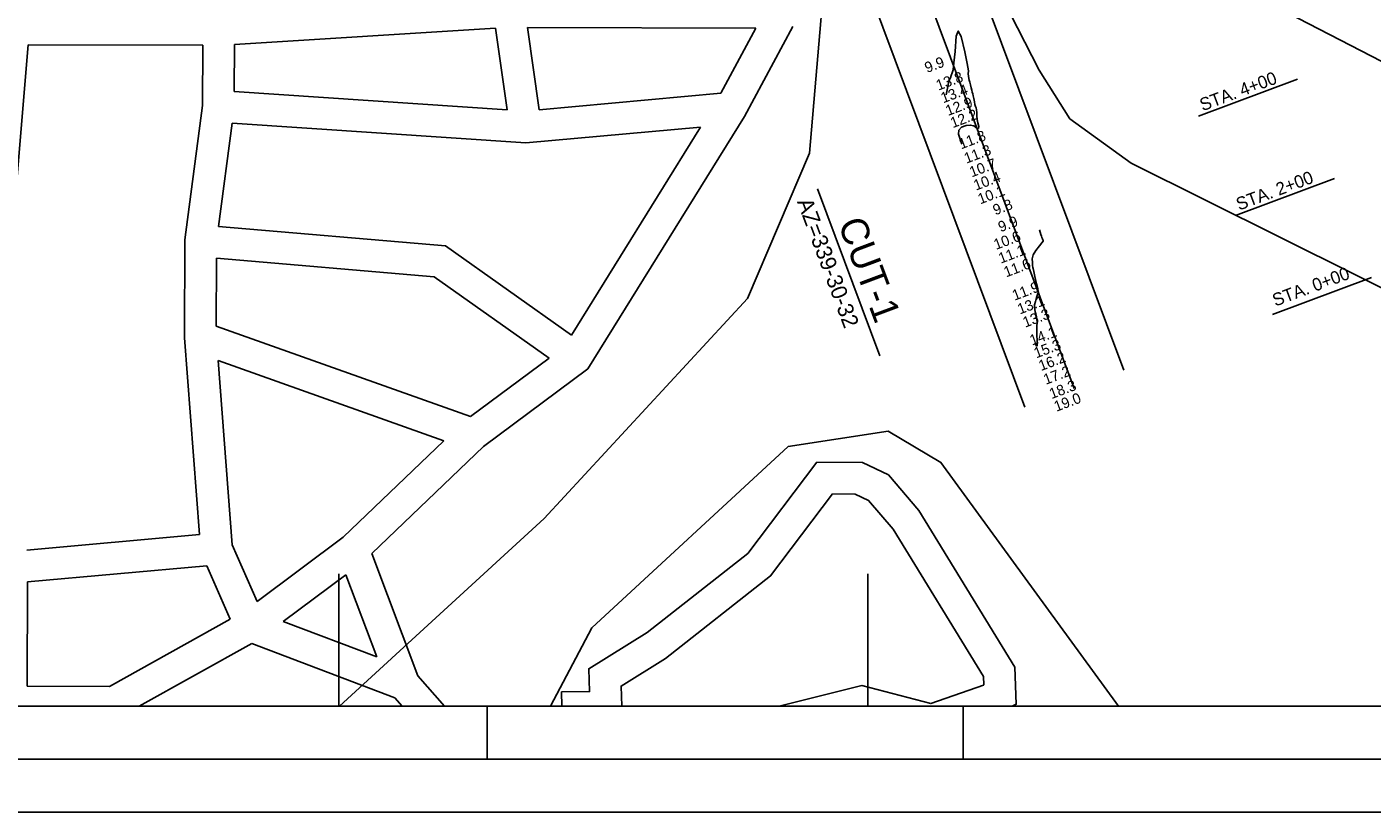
# Model space of a CAD drawing. Extents: x 503330 to 511530, y 1310349 to 1316149.
# Drawn here: x 506410 to 508954, y 1310349 to 1311832 of the extents above; entities that cross this region are included whole.
import ezdxf

# ---------------------------------------------------------------- set-up
doc = ezdxf.new("R2010")
doc.units = 0
for name, color, linetype in [('G-ANNO-TTLB', 7, 'Continuous'), ('Level 1', 7, 'Continuous'), ('Level 2', 7, 'Continuous'), ('Level 32', 7, 'Continuous'), ('Level 49', 7, 'Continuous'), ('Level 5', 7, 'Continuous'), ('Level 50', 7, 'Continuous'), ('Level 51', 7, 'Continuous'), ('Level 56', 7, 'Continuous'), ('Level 6', 7, 'Continuous')]:
    doc.layers.add(name, color=color, linetype=linetype)

msp = doc.modelspace()

# ---------------------------------------------------------------- linework, layer by layer
at = {"layer": 'G-ANNO-TTLB'}
for p, q in [((511330.3, 1310548.5), (503680.3, 1310548.5)), ((507280.3, 1310448.5), (507280.3, 1310548.5)), ((508180.3, 1310448.5), (508180.3, 1310548.5)), ((503430.3, 1310448.5), (511430.3, 1310448.5))]:
    msp.add_line(p, q, dxfattribs=at)
for points in [[(503330.3, 1310348.5), (511530.3, 1310348.5), (511530.3, 1316148.5), (503330.3, 1316148.5)], [(503330.3, 1310348.5), (511530.3, 1310348.5), (511530.3, 1316148.5), (503330.3, 1316148.5)], [(503330.3, 1316148.5), (511530.3, 1316148.5), (511530.3, 1310348.5), (503330.3, 1310348.5)]]:
    msp.add_lwpolyline(points, close=True, dxfattribs=at)
at = {"layer": 'Level 1'}
for points in [[(508148.3, 1311704.1), (508151.3, 1311720.1), (508152.9, 1311726.8), (508154.6, 1311732.1), (508156.4, 1311736.1), (508158.1, 1311740.6), (508159.8, 1311745.8), (508161.4, 1311751.4), (508163.2, 1311764.8), (508165.3, 1311786), (508167.5, 1311815), (508171.3, 1311824.5), (508176.7, 1311814.5), (508183.7, 1311785), (508188.2, 1311763.4), (508190.4, 1311749.7), (508190.2, 1311744), (508190.4, 1311739.1), (508191, 1311735.1), (508192, 1311731.9), (508193.1, 1311727.9), (508194.3, 1311723.1), (508195.6, 1311717.4), (508196.7, 1311712.6), (508197.7, 1311708.9), (508198.6, 1311706.1), (508199.6, 1311702.1), (508200.6, 1311696.9), (508201.8, 1311690.6), (508202.9, 1311685.6), (508203.9, 1311681.9), (508205, 1311679.7), (508205.7, 1311676), (508206.2, 1311670.9), (508206.3, 1311664.3), (508207, 1311657.6), (508208.3, 1311650.9), (508210.2, 1311644), (508209.5, 1311640.7), (508206.3, 1311641.2), (508200.6, 1311645.3), (508193.9, 1311646.9), (508186.1, 1311646), (508177.4, 1311642.7), (508172.6, 1311637.2), (508171.8, 1311629.7), (508178.2, 1311610.5)], [(508324.8, 1311448.7), (508327.7, 1311440.3), (508328.8, 1311437), (508329.6, 1311434.7), (508330, 1311433.3), (508330.5, 1311431.8), (508331, 1311430.3), (508331.5, 1311428.7), (508331.8, 1311427.7), (508331.9, 1311427.3), (508331.8, 1311427.4), (508329.4, 1311424.6), (508324.7, 1311418.8), (508317.7, 1311409.9), (508313.2, 1311401.7), (508311.1, 1311394), (508311.4, 1311386.9), (508311.8, 1311381.6), (508312.2, 1311378), (508312.6, 1311376.1), (508314, 1311370.3), (508316.2, 1311360.5), (508319.4, 1311346.7), (508321.5, 1311337.4), (508322.6, 1311332.4), (508322.7, 1311331.9), (508322.7, 1311331.2), (508322.5, 1311330.5), (508322.2, 1311329.7), (508321.2, 1311326.6), (508319.5, 1311321.2), (508317.1, 1311313.5), (508315.7, 1311307.2), (508315.3, 1311302.1), (508315.9, 1311298.3), (508316.8, 1311294.2), (508317.8, 1311289.9), (508319.1, 1311285.2), (508319.9, 1311279.8), (508320.2, 1311273.6), (508320, 1311266.6), (508319.9, 1311260.7), (508319.8, 1311256.1), (508319.8, 1311252.7), (508320, 1311247.8), (508320.2, 1311241.5), (508320.6, 1311233.8), (508320.4, 1311229.7), (508319.5, 1311229.2), (508316.4, 1311235.4)]]:
    msp.add_lwpolyline(points, dxfattribs=at)
at = {"layer": 'Level 2'}
for p, q in [((507000, 1310548.5), (507000, 1310798.5)), ((508000, 1310548.5), (508000, 1310798.5))]:
    msp.add_line(p, q, dxfattribs=at)
at = {"layer": 'Level 32'}
for p, q in [((508577, 1311971.1), (509264.6, 1311616)), ((507356.6, 1311831.6), (507379, 1311676)), ((507788.4, 1311830), (507356.6, 1311831.6)), ((507858.2, 1311833.2), (507766.9, 1311663.4)), ((507296.2, 1311830.1), (506802.8, 1311799.3)), ((507296.2, 1311830.1), (507318.4, 1311675.9)), ((507788.4, 1311830), (507722.2, 1311706.9)), ((506413, 1311798.8), (506381.7, 1311428.6)), ((506742.8, 1311797.6), (506413, 1311798.8)), ((506742.8, 1311797.6), (506742.3, 1311684.1)), ((506802.8, 1311799.3), (506802.4, 1311710.1)), ((507318.4, 1311675.9), (506802.4, 1311710.1)), ((507722.2, 1311706.9), (507379, 1311676)), ((506742.3, 1311684.1), (506709.1, 1311429.7)), ((507766.9, 1311663.4), (507471.1, 1311186.2)), ((506798.4, 1311650.3), (506772.9, 1311455)), ((507353.7, 1311613.4), (506798.4, 1311650.3)), ((507683.8, 1311643.2), (507353.7, 1311613.4)), ((507683.8, 1311643.2), (507439.9, 1311249.8)), ((506709.1, 1311429.7), (506708.4, 1311244.8)), ((506769, 1311395.1), (506768.5, 1311267.1)), ((507249.3, 1311095.9), (506768.5, 1311267.1)), ((506708.4, 1311244.8), (506737, 1310873.1)), ((507198.5, 1311050.2), (506771.8, 1311202.2)), ((506771.8, 1311202.2), (506798.7, 1310853.3)), ((507397.6, 1311206.3), (507249.3, 1311095.9)), ((507471.1, 1311186.2), (507273.7, 1311039.3)), ((507198.5, 1311050.2), (507008.1, 1310867.9)), ((507273.7, 1311039.3), (507062.5, 1310837)), ((506737, 1310873.1), (506410, 1310843.7)), ((507008.1, 1310867.9), (506845.5, 1310746.8)), ((506798.7, 1310853.3), (506845.5, 1310746.8)), ((506750.4, 1310814.1), (506411.5, 1310783.6)), ((506750.4, 1310814.1), (506794.8, 1310713.1)), ((507062.5, 1310837), (507149.5, 1310605.8)), ((507013.4, 1310797.1), (506895, 1310708.9)), ((507013.4, 1310797.1), (507071.9, 1310641.7)), ((506411.5, 1310783.6), (506410.7, 1310586.4)), ((506794.8, 1310713.1), (506566.6, 1310585.8)), ((507071.9, 1310641.7), (506895, 1310708.9)), ((506835.6, 1310667.2), (506622.9, 1310548.5)), ((507105.8, 1310564.7), (506835.6, 1310667.2)), ((506566.6, 1310585.8), (506410.7, 1310586.4)), ((507149.5, 1310605.8), (507200, 1310548.5)), ((507105.8, 1310564.7), (507120, 1310548.5)), ((507421.5, 1310548.5), (507421.4, 1310576.1))]:
    msp.add_line(p, q, dxfattribs=at)
for points in [[(507439.9, 1311249.8), (507201.7, 1311418.9), (506772.9, 1311455)], [(507397.6, 1311206.3), (507180.3, 1311360.4), (506769, 1311395.1)], [(508273.3, 1310548.5), (508280.8, 1310552.3), (508278.5, 1310622.4), (508096.9, 1310918.3), (508039.2, 1310985.8), (507990.3, 1311009.5), (507904, 1311009.8), (507773.3, 1310837.4), (507583, 1310687.8), (507472.5, 1310619.5), (507474.1, 1310576.3), (507421.4, 1310576.1)], [(507832.1, 1310548.5), (507832.4, 1310548.7), (507988.8, 1310587.6), (508119.2, 1310553.7), (508218.8, 1310588.5), (508219.6, 1310588.9), (508219, 1310604.6), (508048.2, 1310882.9), (508001.7, 1310937.3), (507976.5, 1310949.5), (507933.7, 1310949.7), (507816.4, 1310795), (507617.5, 1310638.5), (507533.8, 1310586.8), (507535.1, 1310548.5)]]:
    msp.add_lwpolyline(points, dxfattribs=at)
at = {"layer": 'Level 5'}
for points in [[(505794, 1315948.5), (505744.2, 1315800.6), (505760.3, 1315617.2), (505843.1, 1315416.9), (505891.3, 1314808.3), (506024, 1314599.6), (506647.4, 1314056), (507642.5, 1313099.9), (507702.7, 1313024.1), (507718.9, 1312844.3), (507743.6, 1312727.6), (507768.6, 1312719.2), (507933.4, 1312101.9), (507890.2, 1311593.7)], [(508324.1, 1311750.7), (508174.9, 1312042.9), (508101.5, 1312576.5), (508071.4, 1312743.4), (508047.3, 1312868.5), (508036.4, 1312983.7), (507933.5, 1313150.3), (507770.5, 1313344.2), (506282.9, 1314790.5), (506133.6, 1315024.3), (506134.1, 1315191), (506100.8, 1315216.1), (506088.6, 1315786), (506110.2, 1315948.5)], [(508324.1, 1311750.7), (508382.1, 1311658.9), (508498.5, 1311575.2), (509205.9, 1311223), (509455.9, 1311222.3), (509691.3, 1311309.1)], [(507001.3, 1310548.5), (507388.1, 1310903.4), (507772.7, 1311319), (507890.2, 1311593.7)], [(508474.4, 1310548.5), (508138.5, 1311009.5), (508038.6, 1311068.2), (507849.8, 1311039.2), (507478.6, 1310696.9), (507400.2, 1310548.5)]]:
    msp.add_lwpolyline(points, dxfattribs=at)
at = {"layer": 'Level 50'}
for p, q in [((508484.2, 1311183.8), (508141.5, 1312100.8)), ((508296.9, 1311113.8), (507947.6, 1312048.3))]:
    msp.add_line(p, q, dxfattribs=at)
at = {"layer": 'Level 51'}
msp.add_line((508023.1, 1311210.6), (507905, 1311526.6), dxfattribs=at)
at = {"layer": 'Level 56'}
for p, q in [((508625.2, 1311663.5), (508812.6, 1311733.5)), ((508695.2, 1311476.1), (508882.6, 1311546.2)), ((508765.2, 1311288.8), (508952.6, 1311358.8))]:
    msp.add_line(p, q, dxfattribs=at)
at = {"layer": 'Level 6'}
msp.add_line((508390.6, 1311148.8), (508044.6, 1312074.6), dxfattribs=at)

# ---------------------------------------------------------------- texts
at = {"layer": 'Level 49'}
for s, p in [('9.9', (508112.2, 1311745.2)), ('13.8 ', (508133.7, 1311711.9)), ('13.4 ', (508142.7, 1311687.9)), ('12.9 ', (508151.7, 1311663.9)), ('12.2 ', (508160.7, 1311640.9)), ('11.8 ', (508176.7, 1311600.9)), ('11.3 ', (508186.7, 1311573.9)), ('10.7 ', (508196.7, 1311547.9)), ('10.4 ', (508204.7, 1311522.9)), ('10.1 ', (508212.7, 1311496.9)), ('9.8', (508241.2, 1311476.2)), ('9.9', (508251.2, 1311444.2)), ('10.6 ', (508242.7, 1311410.9)), ('11.1 ', (508251.7, 1311384.9)), ('11.6 ', (508261.7, 1311358.9)), ('11.9 ', (508277.7, 1311314.9)), ('13.1 ', (508287.7, 1311288.9)), ('13.3 ', (508297.7, 1311263.9)), ('14.1 ', (508310.7, 1311229.9)), ('15.3 ', (508318.7, 1311205.9)), ('16.2 ', (508327.7, 1311181.9)), ('17.2 ', (508336.7, 1311155.9)), ('18.3 ', (508347.7, 1311128.9)), ('19.0 ', (508356.7, 1311104.9))]:
    msp.add_text(s, height=20, rotation=20.491, dxfattribs=at).set_placement(p)
at = {"layer": 'Level 51'}
for s, height, p in [('AZ=339-30-32', 30, (507866.1, 1311502)), ('CUT-1', 52, (507943.4, 1311461.1))]:
    msp.add_text(s, height=height, rotation=290.491, dxfattribs=at).set_placement(p)
at = {"layer": 'Level 56'}
for s, p in [('STA. 4+00', (508633.2, 1311672.9)), ('STA. 2+00', (508702.1, 1311485.1)), ('STA. 0+00', (508770.7, 1311303.7))]:
    msp.add_text(s, height=24, rotation=20.4909, dxfattribs=at).set_placement(p)

doc.saveas('drawing.dxf')
